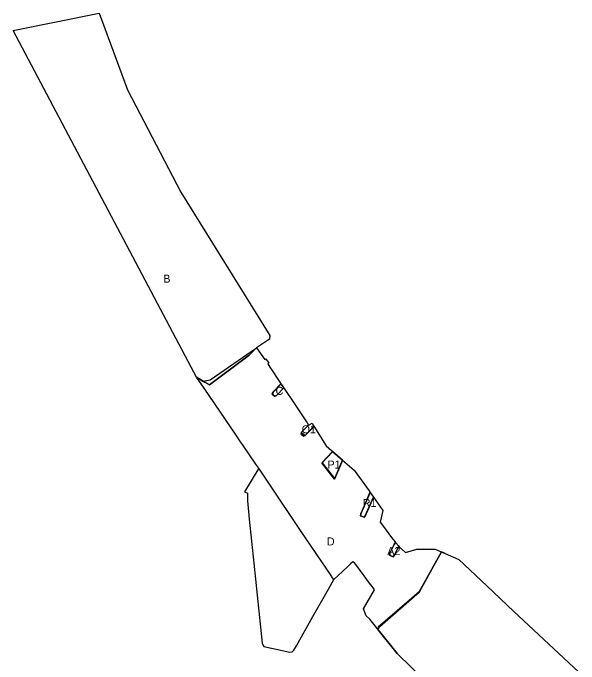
# Model space of a CAD drawing. Extents: x -749314 to -746497, y -1026537 to -1024935.
# Drawn here: x -748528.7 to -748352.2, y -1025145.2 to -1024942.1 of the extents above; entities that cross this region are included whole.
import ezdxf

# ---------------------------------------------------------------- set-up
doc = ezdxf.new("R2010")
doc.units = 0
for name, color, linetype in [('Default', 7, 'Continuous'), ('K_CD1', 7, 'Continuous'), ('K_DOSZDC1', 7, 'Continuous'), ('K_NH_SZDC', 7, 'Continuous')]:
    doc.layers.add(name, color=color, linetype=linetype)

msp = doc.modelspace()

# ---------------------------------------------------------------- linework, layer by layer
at = {"layer": 'Default'}
for points in [[(-748528.65, -1024947.51), (-748501.83, -1024942.1), (-748492.94, -1024966.02), (-748476.37, -1024997.99), (-748448.52, -1025042.72), (-748448.65, -1025043.83), (-748452.75, -1025046.53), (-748454.98, -1025048.85), (-748467.4, -1025058.08), (-748468.84, -1025057.24), (-748471.44, -1025055.71), (-748473.07, -1025052.6)], [(-748438.78, -1025073.49), (-748438.66, -1025072.9), (-748436.47, -1025070.66), (-748435.39, -1025070.12), (-748434.97, -1025070.8), (-748434.81, -1025071.06), (-748437.54, -1025073.95), (-748438.1, -1025074.11)], [(-748432.31, -1025082.44), (-748429, -1025078.94), (-748425.91, -1025081.6), (-748428.38, -1025087.51)], [(-748420.3, -1025098.97), (-748420.22, -1025098.36), (-748417.28, -1025091.73), (-748416.24, -1025093.18), (-748418.8, -1025098.99), (-748419.16, -1025099.43)], [(-748411.26, -1025111.26), (-748411.12, -1025110.67), (-748409.77, -1025107.95), (-748409.43, -1025107.27), (-748408.35, -1025108.48), (-748409.77, -1025111.35), (-748410.15, -1025111.8)]]:
    msp.add_lwpolyline(points, close=True, dxfattribs=at)
at = {"layer": 'K_CD1'}
for points in [[(-748434.81, -1025071.06), (-748431.02, -1025077.2), (-748425.16, -1025082.24), (-748422.22, -1025084.77), (-748417.64, -1025091.22), (-748417.28, -1025091.73), (-748420.22, -1025098.36), (-748420.3, -1025098.97), (-748419.16, -1025099.43), (-748418.8, -1025098.99), (-748416.25, -1025093.19), (-748414.78, -1025095.25), (-748413.29, -1025097.34), (-748414.17, -1025101.02), (-748413.15, -1025102.32), (-748410.63, -1025105.71), (-748409.64, -1025107.04), (-748409.43, -1025107.27), (-748409.77, -1025107.95), (-748411.12, -1025110.67), (-748411.26, -1025111.26), (-748410.15, -1025111.8), (-748409.77, -1025111.35), (-748408.35, -1025108.48), (-748408.45, -1025108.36), (-748408.2, -1025108.64), (-748406.22, -1025110.45), (-748402.71, -1025109.44), (-748397.04, -1025109.41), (-748393.86, -1025110.73), (-748395.07, -1025110.23), (-748402, -1025122.71), (-748411.2, -1025130.6), (-748414.69, -1025133.64), (-748414.72, -1025134.1), (-748414.74, -1025134.54), (-748408.87, -1025141.96), (-748417.35, -1025131.25), (-748418.56, -1025130.15), (-748419.35, -1025128.06), (-748415.95, -1025122.1), (-748416.29, -1025121.58), (-748417.49, -1025119.97), (-748421.18, -1025115), (-748422.17, -1025113.67), (-748422.72, -1025113.4), (-748423.38, -1025114.01), (-748424.26, -1025114.83), (-748425.89, -1025116.35), (-748428.64, -1025118.91), (-748429.31, -1025117.92), (-748429.48, -1025117.66), (-748438.77, -1025103.87), (-748439.41, -1025102.92), (-748448.3, -1025089.73), (-748452.04, -1025084.17), (-748452.96, -1025082.84), (-748457.13, -1025076.71), (-748457.68, -1025075.9), (-748459.08, -1025073.85), (-748469.08, -1025059.18), (-748471.44, -1025055.71), (-748468.84, -1025057.24), (-748467.4, -1025058.08), (-748454.98, -1025048.85), (-748452.75, -1025046.53), (-748450.71, -1025049.35), (-748450.11, -1025050.26), (-748449.78, -1025050.04), (-748448.88, -1025051.39), (-748449.21, -1025051.61), (-748448.56, -1025052.59), (-748447.87, -1025053.63), (-748444.47, -1025058.74), (-748444.71, -1025058.38), (-748445.01, -1025057.93), (-748445.11, -1025057.78), (-748447.64, -1025060.44), (-748447.81, -1025061.05), (-748447.15, -1025061.66), (-748446.51, -1025061.48), (-748444.25, -1025059.09), (-748444.41, -1025058.83), (-748443.92, -1025059.57), (-748443.06, -1025060.87), (-748441.93, -1025062.54), (-748437.75, -1025068.73), (-748436.92, -1025069.96), (-748436.47, -1025070.66), (-748438.66, -1025072.9), (-748438.78, -1025073.49), (-748438.1, -1025074.11), (-748437.54, -1025073.95)], [(-748432.31, -1025082.44), (-748428.38, -1025087.51), (-748425.91, -1025081.6), (-748429, -1025078.94)], [(-748450.78, -1025139.29), (-748450.39, -1025139.79), (-748442.37, -1025141.52), (-748441.63, -1025141.43), (-748441.06, -1025140.95), (-748440.29, -1025139.57), (-748435.15, -1025130.45), (-748430.31, -1025121.86), (-748428.64, -1025118.91), (-748429.31, -1025117.92), (-748429.48, -1025117.66), (-748438.77, -1025103.87), (-748439.41, -1025102.92), (-748448.3, -1025089.73), (-748452.04, -1025084.17), (-748456.48, -1025091.47), (-748455.56, -1025091.97), (-748455.57, -1025094.3), (-748454.97, -1025100.01), (-748453.54, -1025113.72), (-748450.92, -1025138.75)]]:
    msp.add_lwpolyline(points, close=True, dxfattribs=at)
at = {"layer": 'K_DOSZDC1'}
msp.add_lwpolyline([(-748447.81, -1025061.05), (-748447.64, -1025060.44), (-748445.11, -1025057.78), (-748445.01, -1025057.93), (-748444.71, -1025058.38), (-748444.41, -1025058.83), (-748444.25, -1025059.09), (-748446.51, -1025061.48), (-748447.15, -1025061.66)], close=True, dxfattribs=at)
msp.add_lwpolyline([(-748400.03, -1025150.58), (-748408.87, -1025141.96), (-748414.74, -1025134.54), (-748414.72, -1025134.1), (-748414.69, -1025133.64), (-748411.2, -1025130.6), (-748402, -1025122.71), (-748395.07, -1025110.23), (-748393.86, -1025110.73), (-748389.66, -1025112.62), (-748380.93, -1025120.81), (-748372.53, -1025128.89), (-748361.64, -1025138.97), (-748352.17, -1025147.81)], dxfattribs=at)
at = {"layer": 'K_NH_SZDC'}
for points in [[(-748471.44, -1025055.71), (-748469.49, -1025056.97), (-748467.14, -1025056.53), (-748452.75, -1025046.53)], [(-748445.07, -1025057.85), (-748447.4, -1025060.33), (-748447.7, -1025060.96), (-748447.17, -1025061.67), (-748446.55, -1025061.54), (-748444.23, -1025059.1)], [(-748436.48, -1025070.64), (-748438.66, -1025072.95), (-748437.55, -1025073.98), (-748434.79, -1025071.09)], [(-748428.96, -1025078.97), (-748432.25, -1025082.51), (-748428.3, -1025087.48), (-748425.82, -1025081.67)], [(-748417.36, -1025091.61), (-748420.19, -1025098.42), (-748420.28, -1025099.02), (-748419.26, -1025099.36), (-748418.76, -1025099.02), (-748416.21, -1025093.23)], [(-748409.41, -1025107.29), (-748409.75, -1025107.96), (-748411.11, -1025110.68), (-748411.19, -1025111.27), (-748410.1, -1025111.8), (-748409.72, -1025111.36), (-748408.31, -1025108.51)], [(-748414.65, -1025134.66), (-748414.68, -1025134.09), (-748414.31, -1025133.51), (-748401.94, -1025122.75), (-748395.03, -1025110.24)]]:
    msp.add_lwpolyline(points, dxfattribs=at)

# ---------------------------------------------------------------- texts
for s, p in [('B', (-748481.78, -1025026.25)), ('R1', (-748419.6, -1025096.25)), ('D', (-748430.78, -1025108.25)), ('A2', (-748411.94, -1025111.25))]:
    msp.add_text(s, height=2.5).set_placement(p)
for s, p in [('C', (-748446.78, -1025061.25)), ('O1', (-748438.64, -1025073.25)), ('P1', (-748430.6, -1025084.25))]:
    msp.add_text(s, height=2.5, dxfattribs=at).set_placement(p)

doc.saveas('drawing.dxf')
